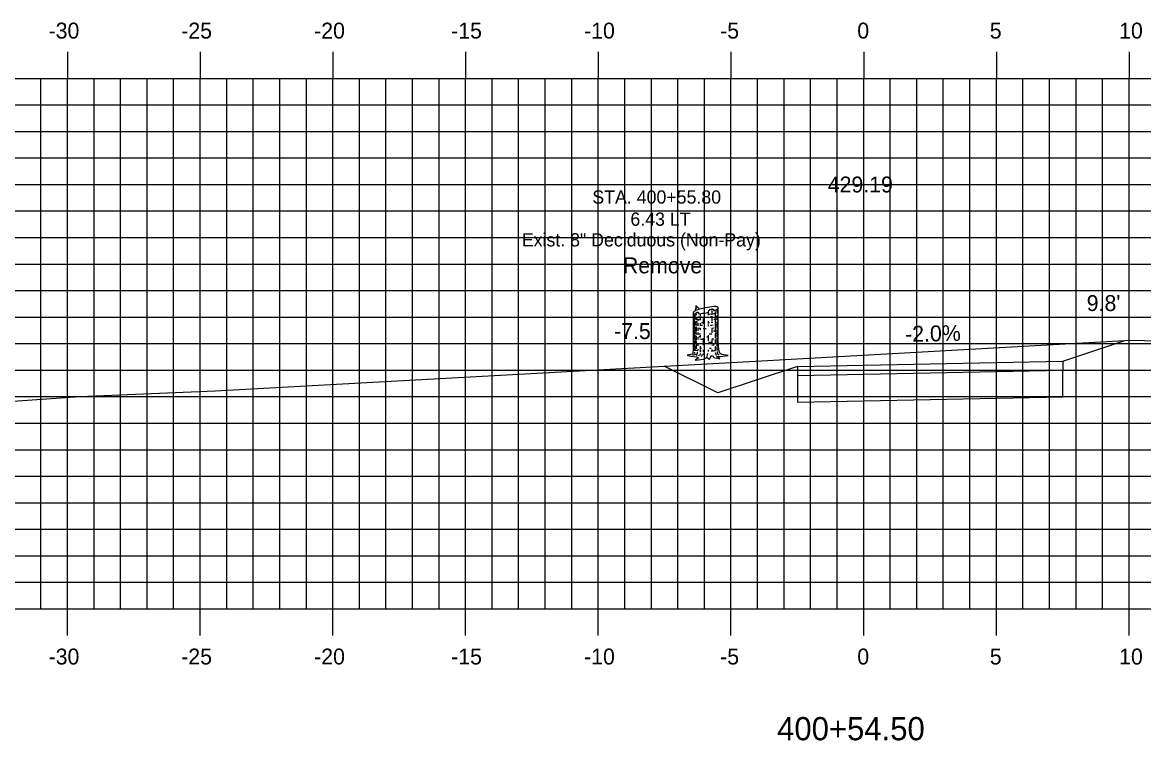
# Model space of a CAD drawing. Extents: x -161 to 764, y 111 to 210.
# Drawn here: x 122.87 to 165.11, y 162.17 to 189.25 of the extents above; entities that cross this region are included whole.
import ezdxf

# ---------------------------------------------------------------- set-up
doc = ezdxf.new("R2010")
doc.units = 0
for name, color, linetype in [('D_Property_Walkway_Paved', 7, 'Continuous'), ('D_Roadway_Centerline_Text', 7, 'Continuous'), ('D_Roadway_SubGrade', 7, 'Continuous'), ('D_Slope_Cut', 7, 'Continuous'), ('D_Text_Monospaced', 7, 'Continuous'), ('D_Text_Standard', 7, 'Continuous'), ('H_V ANNOTATION', 7, 'Continuous'), ('MAJOR', 7, 'Continuous'), ('MINOR', 7, 'Continuous'), ('S_Roadway_Centerline', 7, 'Continuous'), ('S_Trees_Decid_NonPay', 7, 'Continuous')]:
    doc.layers.add(name, color=color, linetype=linetype)

msp = doc.modelspace()

# ---------------------------------------------------------------- linework, layer by layer
at = {"layer": 'D_Property_Walkway_Paved'}
for p, q in [((152.064, 176.281), (162.062, 176.481)), ((152.064, 176.281), (152.064, 175.937)), ((162.062, 176.481), (162.062, 176.137)), ((152.064, 175.937), (162.062, 176.137))]:
    msp.add_line(p, q, dxfattribs=at)
at = {"layer": 'D_Roadway_SubGrade'}
for p, q in [((152.064, 175.937), (152.064, 174.937)), ((162.063, 175.137), (162.062, 176.137)), ((152.064, 174.937), (162.063, 175.137))]:
    msp.add_line(p, q, dxfattribs=at)
at = {"layer": 'D_Slope_Cut'}
for p, q in [((162.062, 176.481), (164.401, 177.26)), ((149.064, 175.281), (147.045, 176.29)), ((152.064, 176.281), (149.064, 175.281))]:
    msp.add_line(p, q, dxfattribs=at)
at = {"layer": 'MAJOR'}
for p, q in [((124.563, 188.143), (124.563, 187.141)), ((129.563, 188.143), (129.563, 187.141)), ((134.563, 188.143), (134.563, 187.141)), ((139.563, 188.143), (139.563, 187.141)), ((144.563, 188.143), (144.563, 187.141)), ((149.563, 188.143), (149.563, 187.141)), ((154.563, 188.143), (154.563, 187.141)), ((159.563, 188.143), (159.563, 187.141)), ((164.563, 188.143), (164.563, 187.141)), ((84.563, 187.141), (224.563, 187.141)), ((84.563, 187.141), (224.563, 187.141)), ((124.563, 167.141), (124.563, 187.141)), ((129.563, 167.141), (129.563, 187.141)), ((134.563, 167.141), (134.563, 187.141)), ((139.563, 167.141), (139.563, 187.141)), ((144.563, 167.141), (144.563, 187.141)), ((149.563, 167.141), (149.563, 187.141)), ((154.563, 167.141), (154.563, 187.141)), ((159.563, 167.141), (159.563, 187.141)), ((164.563, 167.141), (164.563, 187.141)), ((84.563, 182.141), (224.563, 182.141)), ((84.563, 177.141), (224.563, 177.141)), ((84.563, 172.141), (224.563, 172.141)), ((84.563, 167.141), (224.563, 167.141)), ((84.563, 167.141), (224.563, 167.141)), ((124.563, 166.139), (124.563, 167.141)), ((129.563, 166.139), (129.563, 167.141)), ((134.563, 166.139), (134.563, 167.141)), ((139.563, 166.139), (139.563, 167.141)), ((144.563, 166.139), (144.563, 167.141)), ((149.563, 166.139), (149.563, 167.141)), ((154.563, 166.139), (154.563, 167.141)), ((159.563, 166.139), (159.563, 167.141)), ((164.563, 166.139), (164.563, 167.141))]:
    msp.add_line(p, q, dxfattribs=at)
at = {"layer": 'MINOR'}
for p, q in [((123.563, 167.141), (123.563, 187.141)), ((125.563, 167.141), (125.563, 187.141)), ((126.563, 167.141), (126.563, 187.141)), ((127.563, 167.141), (127.563, 187.141)), ((128.563, 167.141), (128.563, 187.141)), ((130.563, 167.141), (130.563, 187.141)), ((131.563, 167.141), (131.563, 187.141)), ((132.563, 167.141), (132.563, 187.141)), ((133.563, 167.141), (133.563, 187.141)), ((135.563, 167.141), (135.563, 187.141)), ((136.563, 167.141), (136.563, 187.141)), ((137.563, 167.141), (137.563, 187.141)), ((138.563, 167.141), (138.563, 187.141)), ((140.563, 167.141), (140.563, 187.141)), ((141.563, 167.141), (141.563, 187.141)), ((142.563, 167.141), (142.563, 187.141)), ((143.563, 167.141), (143.563, 187.141)), ((145.563, 167.141), (145.563, 187.141)), ((146.563, 167.141), (146.563, 187.141)), ((147.563, 167.141), (147.563, 187.141)), ((148.563, 167.141), (148.563, 187.141)), ((150.563, 167.141), (150.563, 187.141)), ((151.563, 167.141), (151.563, 187.141)), ((152.563, 167.141), (152.563, 187.141)), ((153.563, 167.141), (153.563, 187.141)), ((155.563, 167.141), (155.563, 187.141)), ((156.563, 167.141), (156.563, 187.141)), ((157.563, 167.141), (157.563, 187.141)), ((158.563, 167.141), (158.563, 187.141)), ((160.563, 167.141), (160.563, 187.141)), ((161.563, 167.141), (161.563, 187.141)), ((162.563, 167.141), (162.563, 187.141)), ((163.563, 167.141), (163.563, 187.141)), ((84.563, 186.141), (224.563, 186.141)), ((84.563, 185.141), (224.563, 185.141)), ((84.563, 184.141), (224.563, 184.141)), ((84.563, 183.141), (224.563, 183.141)), ((84.563, 181.141), (224.563, 181.141)), ((84.563, 180.141), (224.563, 180.141)), ((84.563, 179.141), (224.563, 179.141)), ((84.563, 178.141), (224.563, 178.141)), ((84.563, 176.141), (224.563, 176.141)), ((84.563, 175.141), (224.563, 175.141)), ((84.563, 174.141), (224.563, 174.141)), ((84.563, 173.141), (224.563, 173.141)), ((84.563, 171.141), (224.563, 171.141)), ((84.563, 170.141), (224.563, 170.141)), ((84.563, 169.141), (224.563, 169.141)), ((84.563, 168.141), (224.563, 168.141))]:
    msp.add_line(p, q, dxfattribs=at)
at = {"layer": 'S_Roadway_Centerline'}
msp.add_lwpolyline([(84.563, 173.937), (86.565, 173.962), (104.807, 174.158), (105.264, 174.178), (106.296, 174.117), (107.265, 173.972), (107.828, 174.003), (110.477, 174.125), (125.033, 175.141), (130.13, 175.365), (150.707, 176.49), (164.616, 177.272), (172.022, 177.096), (179.352, 177.108), (186.535, 177.007), (193.367, 177.096), (200.259, 176.65), (200.943, 176.413), (208.506, 176.123), (214.429, 175.907), (217.362, 175.08), (224.563, 174.564)], dxfattribs=at)
at = {"layer": 'S_Trees_Decid_NonPay'}
for p, q in [((148.402, 178.269), (148.402, 178.191)), ((148.699, 178.322), (148.699, 178.215)), ((148.846, 178.368), (148.846, 178.219)), ((148.965, 178.351), (148.965, 178.05)), ((149.033, 178.437), (149.033, 178.343)), ((148.175, 178.194), (148.175, 178.112)), ((148.175, 178.042), (148.175, 177.912)), ((148.175, 177.89), (148.175, 177.708)), ((148.202, 178.264), (148.202, 178.046)), ((148.202, 177.977), (148.202, 177.826)), ((148.245, 178.259), (148.245, 178.207)), ((148.245, 178.104), (148.245, 178.021)), ((148.245, 177.987), (148.245, 177.912)), ((148.245, 177.885), (148.245, 177.826)), ((148.315, 178.086), (148.315, 177.999)), ((148.315, 177.929), (148.315, 177.807)), ((148.402, 178.104), (148.402, 178.019)), ((148.402, 177.908), (148.402, 177.807)), ((148.52, 178.086), (148.52, 177.885)), ((148.699, 177.987), (148.699, 177.9)), ((148.699, 177.865), (148.699, 177.795)), ((148.846, 178.172), (148.846, 178.003)), ((148.965, 178.021), (148.965, 177.89)), ((148.965, 177.856), (148.965, 177.575)), ((149.033, 178.116), (149.033, 178.034)), ((149.033, 177.964), (149.033, 177.713)), ((148.175, 177.661), (148.175, 177.414)), ((148.202, 177.721), (148.202, 177.643)), ((148.202, 177.616), (148.202, 177.509)), ((148.202, 177.474), (148.202, 177.373)), ((148.245, 177.773), (148.245, 177.592)), ((148.245, 177.56), (148.245, 177.478)), ((148.245, 177.424), (148.245, 177.254)), ((148.315, 177.732), (148.315, 177.618)), ((148.315, 177.556), (148.315, 177.474)), ((148.402, 177.723), (148.402, 177.647)), ((148.402, 177.462), (148.402, 177.364)), ((148.699, 177.462), (148.699, 177.239)), ((148.846, 177.697), (148.846, 177.548)), ((148.965, 177.505), (148.965, 177.361)), ((149.033, 177.63), (149.033, 177.4)), ((148.173, 177.248), (148.174, 176.988)), ((148.175, 177.395), (148.175, 177.301)), ((148.202, 177.347), (148.202, 177.165)), ((148.202, 177.062), (148.202, 176.87)), ((148.245, 177.22), (148.245, 176.941)), ((148.315, 177.387), (148.315, 177.29)), ((148.315, 177.161), (148.315, 177.062)), ((148.402, 177.04), (148.402, 176.815)), ((148.52, 177.348), (148.52, 177.161)), ((148.52, 177.13), (148.52, 177.077)), ((148.846, 177.279), (148.846, 177.126)), ((148.965, 177.29), (148.965, 177.149)), ((148.965, 177.048), (148.965, 176.866)), ((149.033, 177.33), (149.033, 177.169)), ((149.033, 177.153), (149.033, 177.048)), ((149.033, 177.011), (149.033, 176.887)), ((148.122, 176.702), (148.189, 176.733)), ((148.204, 176.823), (148.169, 176.772)), ((148.175, 176.949), (148.175, 176.875)), ((148.245, 176.888), (148.245, 176.863)), ((148.315, 176.933), (148.315, 176.874)), ((148.52, 176.901), (148.52, 176.811)), ((148.659, 176.62), (148.694, 176.765)), ((148.699, 176.906), (148.699, 176.84)), ((148.846, 176.914), (148.846, 176.836)), ((148.966, 176.807), (149.007, 176.71))]:
    msp.add_line(p, q, dxfattribs=at)
for points in [[(148.134, 178.301), (148.134, 176.889), (148.111, 176.741), (147.908, 176.698), (148.048, 176.662), (148.266, 176.644), (148.336, 176.601), (148.214, 176.512), (148.546, 176.555), (148.659, 176.62), (148.752, 176.559), (148.808, 176.638), (148.799, 176.675), (148.861, 176.677), (148.913, 176.62), (149.145, 176.568), (149.018, 176.656), (149.149, 176.658), (149.458, 176.696), (149.219, 176.727), (149.141, 176.784), (149.102, 176.906), (149.085, 177.26), (149.085, 178.493)], [(148.229, 178.382), (148.233, 178.477), (148.247, 178.45), (148.247, 178.571), (148.268, 178.508), (148.283, 178.54), (148.299, 178.485), (148.315, 178.502), (148.334, 178.493), (148.353, 178.426)], [(148.251, 178.258), (148.268, 178.32), (148.291, 178.308), (148.321, 178.343), (148.355, 178.265)], [(148.721, 178.327), (148.729, 178.394), (148.754, 178.399), (148.762, 178.433), (148.793, 178.419), (148.808, 178.433), (148.832, 178.41), (148.855, 178.419), (148.867, 178.468), (148.875, 178.425), (148.906, 178.433), (148.909, 178.382)], [(148.173, 176.749), (148.252, 176.733), (148.268, 176.689)], [(148.252, 176.733), (148.295, 176.767), (148.303, 176.815)], [(148.399, 176.767), (148.394, 176.698), (148.33, 176.685)], [(148.511, 176.761), (148.511, 176.725), (148.46, 176.694), (148.443, 176.644)], [(149.036, 176.844), (149.044, 176.767), (149.123, 176.718)]]:
    msp.add_lwpolyline(points, dxfattribs=at)
for centre, radius, start, end in [((148.158, 178.301), 0.0237, 161.8277, 175.7722), ((148.152, 178.302), 0.0179, 175.7722, 191.8277), ((148.152, 178.302), 0.0179, 191.8277, 207.8832), ((148.167, 178.298), 0.0336, 143.0514, 161.8277), ((148.157, 178.304), 0.0237, 207.8832, 221.8277), ((148.164, 178.311), 0.0336, 221.8277, 240.604), ((148.215, 178.262), 0.0935, 131.8277, 143.0514), ((148.194, 178.363), 0.0935, 240.604, 251.8277), ((148.367, 178.092), 0.322, 109.7098, 131.8277), ((148.265, 178.58), 0.322, 251.8277, 267.5521), ((149.104, 176.035), 2.507, 101.8277, 109.7098), ((148.115, 180.76), 2.507, 275.4987, 281.8277), ((149.104, 176.035), 2.507, 93.9457, 101.8277), ((148.115, 180.76), 2.507, 281.8277, 284.0013), ((148.61, 180.607), 2.356, 276.7201, 278.1032), ((148.115, 180.76), 2.507, 288.4719, 289.7098), ((148.954, 178.215), 0.322, 71.8277, 93.9457), ((148.896, 178.597), 0.326, 278.1032, 282.1964), ((148.852, 178.703), 0.322, 289.7098, 311.8277), ((148.896, 178.597), 0.326, 291.6757, 300), ((149.025, 178.432), 0.0935, 60.604, 71.8277), ((149.01, 178.4), 0.0984, 300, 311.2506), ((149.004, 178.533), 0.0935, 311.8277, 323.0514), ((149.054, 178.484), 0.0336, 41.8277, 60.604), ((149.052, 178.353), 0.0356, 311.2506, 330), ((149.062, 178.49), 0.0237, 27.8832, 41.8277), ((149.052, 178.497), 0.0336, 323.0514, 341.8277), ((149.061, 178.347), 0.0252, 330, 343.9485), ((149.067, 178.493), 0.0179, 11.8277, 27.8832), ((149.067, 178.493), 0.0179, 355.7722, 11.8277), ((149.061, 178.494), 0.0237, 341.8277, 355.7722), ((149.067, 178.346), 0.0191, 360, 16.0515), ((149.067, 178.346), 0.0191, 343.9485, 360), ((148.154, 178.233), 0.0191, 173.8872, 180), ((148.154, 178.233), 0.0191, 180, 196.0515), ((148.16, 178.234), 0.0252, 196.0515, 210), ((148.154, 178.132), 0.0191, 173.8872, 180), ((148.154, 178.132), 0.0191, 180, 196.0515), ((148.16, 178.133), 0.0252, 196.0515, 210), ((148.154, 178.029), 0.0191, 173.8872, 180), ((148.154, 178.029), 0.0191, 180, 196.0515), ((148.154, 177.924), 0.0191, 173.8872, 180), ((148.154, 177.924), 0.0191, 180, 196.0515), ((148.16, 177.925), 0.0252, 196.0515, 210), ((148.169, 178.239), 0.0356, 210, 228.7494), ((148.169, 178.139), 0.0356, 210, 228.7494), ((148.169, 177.931), 0.0356, 210, 228.7494), ((148.21, 178.287), 0.0984, 228.7494, 240), ((148.21, 178.186), 0.0984, 228.7494, 240), ((148.21, 177.978), 0.0984, 228.7494, 240), ((148.324, 178.484), 0.326, 240, 248.0494), ((148.324, 178.383), 0.326, 240, 248.0494), ((148.324, 178.175), 0.326, 240, 248.0494), ((148.324, 178.28), 0.326, 255.9618, 261.8968), ((148.324, 178.175), 0.326, 255.9618, 261.8968), ((148.324, 178.383), 0.326, 260.9146, 261.8968), ((148.61, 180.393), 2.356, 261.8968, 264.9353), ((148.61, 180.29), 2.356, 261.8968, 262.6162), ((148.61, 180.185), 2.356, 261.8968, 262.8131), ((148.61, 180.494), 2.356, 263.2266, 266.8519), ((148.61, 180.29), 2.356, 266.0259, 267.8019), ((148.61, 180.393), 2.356, 267.8019, 269.1881), ((148.61, 180.607), 2.356, 272.1614, 274.76), ((148.61, 180.29), 2.356, 272.1614, 273.4964), ((148.61, 180.494), 2.356, 272.6327, 275.758), ((148.61, 180.185), 2.356, 274.3638, 276.7318), ((148.61, 180.29), 2.356, 275.0054, 276.6587), ((148.61, 180.393), 2.356, 277.4481, 278.1032), ((148.896, 178.383), 0.326, 278.1032, 289.5833), ((148.896, 178.484), 0.326, 282.1964, 299.0901), ((148.896, 178.28), 0.326, 282.1964, 288.3169), ((148.896, 178.175), 0.326, 282.1964, 294.8455), ((148.896, 178.383), 0.326, 296.4281, 300), ((148.896, 178.28), 0.326, 296.757, 300), ((149.01, 178.186), 0.0984, 300, 311.2506), ((149.01, 178.083), 0.0984, 300, 311.2506), ((149.052, 178.139), 0.0356, 311.2506, 330), ((149.052, 178.036), 0.0356, 311.2506, 330), ((149.061, 178.133), 0.0252, 330, 343.9485), ((149.061, 178.03), 0.0252, 330, 343.9485), ((149.067, 178.132), 0.0191, 360, 16.0515), ((149.067, 178.132), 0.0191, 343.9485, 360), ((149.067, 178.029), 0.0191, 360, 16.0515), ((149.067, 178.029), 0.0191, 343.9485, 360), ((148.153, 177.694), 0.0191, 173.8872, 180), ((148.153, 177.694), 0.0191, 180, 196.0515), ((148.154, 177.809), 0.0191, 173.8872, 180), ((148.154, 177.809), 0.0191, 180, 196.0515), ((148.16, 177.81), 0.0252, 196.0515, 210), ((148.159, 177.696), 0.0252, 196.0515, 210), ((148.154, 177.489), 0.0191, 173.8872, 180), ((148.154, 177.489), 0.0191, 180, 196.0515), ((148.16, 177.491), 0.0252, 196.0515, 210), ((148.168, 177.701), 0.0356, 210, 228.7494), ((148.156, 177.594), 0.0191, 173.8872, 180), ((148.156, 177.594), 0.0191, 180, 196.0515), ((148.169, 177.816), 0.0356, 210, 228.7494), ((148.162, 177.596), 0.0252, 196.0515, 210), ((148.169, 177.496), 0.0356, 210, 228.7494), ((148.171, 177.601), 0.0356, 210, 228.7494), ((148.21, 177.863), 0.0984, 228.7494, 240), ((148.209, 177.748), 0.0984, 228.7494, 240), ((148.21, 177.543), 0.0984, 228.7494, 240), ((148.213, 177.648), 0.0984, 228.7494, 240), ((148.323, 177.946), 0.326, 240, 242.9942), ((148.324, 178.06), 0.326, 240, 255.9618), ((148.324, 177.741), 0.326, 240, 242.8475), ((148.326, 177.845), 0.326, 240, 247.5951), ((148.323, 177.946), 0.326, 248.1902, 256.0964), ((148.324, 177.741), 0.326, 248.0494, 255.9618), ((148.61, 180.07), 2.356, 262.8131, 264.9353), ((148.613, 179.855), 2.356, 262.7545, 265.0266), ((148.61, 180.185), 2.356, 264.9353, 266.9933), ((148.61, 180.07), 2.356, 267.586, 270), ((148.61, 180.07), 2.356, 270, 270.4422), ((148.613, 179.855), 2.356, 273.1471, 275.6557), ((148.61, 180.07), 2.356, 275.2089, 277.3412), ((148.609, 179.956), 2.356, 277.1385, 278.1032), ((148.896, 177.946), 0.326, 278.1032, 282.3301), ((148.899, 177.845), 0.326, 283.0921, 300), ((148.896, 177.946), 0.326, 292.1344, 300), ((148.896, 178.06), 0.326, 294.8455, 300), ((148.896, 177.741), 0.326, 294.8455, 300), ((149.01, 177.863), 0.0984, 300, 311.2506), ((149.009, 177.748), 0.0984, 300, 311.2506), ((149.01, 177.543), 0.0984, 300, 311.2506), ((149.051, 177.701), 0.0356, 311.2506, 330), ((149.052, 177.816), 0.0356, 311.2506, 330), ((149.052, 177.496), 0.0356, 311.2506, 330), ((149.061, 177.81), 0.0252, 330, 343.9485), ((149.06, 177.696), 0.0252, 330, 343.9485), ((149.061, 177.491), 0.0252, 330, 343.9485), ((149.066, 177.694), 0.0191, 360, 16.0515), ((149.066, 177.694), 0.0191, 343.9485, 360), ((149.067, 177.809), 0.0191, 360, 16.0515), ((149.067, 177.809), 0.0191, 343.9485, 360), ((149.067, 177.489), 0.0191, 360, 16.0515), ((149.067, 177.489), 0.0191, 343.9485, 360), ((149.069, 177.594), 0.0191, 360, 16.0515), ((148.154, 177.399), 0.0191, 173.8872, 180), ((148.158, 177.17), 0.0191, 173.8872, 180), ((148.158, 177.17), 0.0191, 180, 196.0515), ((148.164, 177.172), 0.0252, 196.0515, 210), ((148.173, 177.177), 0.0356, 210, 228.7494), ((148.214, 177.224), 0.0984, 228.7494, 240), ((148.333, 177.311), 0.326, 240, 246.3456), ((148.324, 177.537), 0.326, 248.0494, 255.9618), ((148.328, 177.421), 0.326, 255.2259, 261.8968), ((148.614, 179.431), 2.356, 261.8968, 262.7137), ((148.61, 179.751), 2.356, 263.572, 264.9353), ((148.61, 179.66), 2.356, 264.7274, 267.8019), ((148.61, 179.751), 2.356, 270.9946, 272.1614), ((148.61, 179.547), 2.356, 272.531, 275.758), ((148.61, 179.66), 2.356, 275.5135, 277.4157), ((148.614, 179.431), 2.356, 275.5148, 277.7774), ((148.896, 177.65), 0.326, 286.0817, 298.061), ((148.9, 177.421), 0.326, 294.0625, 300), ((148.905, 177.311), 0.326, 298.0903, 300), ((149.014, 177.224), 0.0984, 300, 311.2506), ((149.019, 177.114), 0.0984, 300, 311.2506), ((149.056, 177.177), 0.0356, 311.2506, 330), ((149.061, 177.066), 0.0356, 311.2506, 330), ((149.065, 177.172), 0.0252, 330, 343.9485), ((149.071, 177.17), 0.0191, 360, 16.0515), ((149.071, 177.17), 0.0191, 343.9485, 360), ((149.07, 177.061), 0.0252, 330, 343.9485), ((149.075, 177.06), 0.0191, 360, 16.0515), ((149.075, 177.06), 0.0191, 343.9485, 360), ((148.168, 176.949), 0.0191, 173.8872, 180), ((148.168, 176.949), 0.0191, 180, 196.0515), ((148.174, 176.951), 0.0252, 196.0515, 210), ((148.183, 176.956), 0.0356, 210, 228.7494), ((148.225, 177.003), 0.0984, 228.7494, 240), ((148.338, 177.201), 0.326, 245.2906, 261.8968), ((148.625, 179.211), 2.356, 261.8968, 262.4597), ((148.619, 179.321), 2.356, 264.7171, 265.8136), ((148.625, 179.211), 2.356, 264.5833, 265.4449), ((148.619, 179.321), 2.356, 273.1842, 275.0911), ((148.625, 179.211), 2.356, 276.4667, 278.1032), ((148.911, 177.201), 0.326, 278.1032, 279.6166), ((148.911, 177.201), 0.326, 292.0839, 300), ((149.025, 177.003), 0.0984, 300, 311.2506), ((149.066, 176.956), 0.0356, 311.2506, 330), ((149.075, 176.951), 0.0252, 330, 343.9485), ((149.081, 176.949), 0.0191, 360, 16.0515), ((149.081, 176.949), 0.0191, 343.9485, 360)]:
    msp.add_arc(centre, radius, start, end, dxfattribs=at)

# ---------------------------------------------------------------- texts
at = {"layer": 'D_Roadway_Centerline_Text'}
msp.add_text('429.19', height=0.6, dxfattribs=at).set_placement((153.209, 182.839))
at = {"layer": 'D_Text_Monospaced'}
for s, height, p in [('STA. 400+55.80', 0.49998, (144.339, 182.417)), ('6.43 LT', 0.5, (145.773, 181.583)), ('Exist. 8" Deciduous (Non-Pay)', 0.49998, (141.681, 180.803))]:
    msp.add_text(s, height=height, dxfattribs=at).set_placement(p)
at = {"layer": 'D_Text_Standard'}
for s, p in [('Remove', (145.49, 179.789)), ("9.8'", (162.966, 178.368)), ('-7.5', (145.157, 177.312))]:
    msp.add_text(s, height=0.6, dxfattribs=at).set_placement(p)
msp.add_text('-2.0%', height=0.6, rotation=1.1458, dxfattribs=at).set_placement((156.13, 177.202))
at = {"layer": 'H_V ANNOTATION'}
for s, height, p in [('-30', 0.6, (123.851, 188.641)), ('-25', 0.6, (128.849, 188.641)), ('-20', 0.6, (133.857, 188.641)), ('-10', 0.6, (144.028, 188.641)), ('0', 0.6, (154.322, 188.641)), ('10', 0.6, (164.188, 188.641)), ('-15', 0.6, (139.02, 188.641)), ('-5', 0.6, (149.154, 188.641)), ('5', 0.6, (159.314, 188.641)), ('-30', 0.6, (123.851, 165.041)), ('-25', 0.6, (128.849, 165.041)), ('-20', 0.6, (133.857, 165.041)), ('-15', 0.6, (139.02, 165.041)), ('-10', 0.6, (144.028, 165.041)), ('-5', 0.6, (149.154, 165.041)), ('0', 0.6, (154.322, 165.041)), ('5', 0.6, (159.314, 165.041)), ('10', 0.6, (164.188, 165.041)), ('400+54.50', 0.875, (151.301, 162.184))]:
    msp.add_text(s, height=height, rotation=360, dxfattribs=at).set_placement(p)

doc.saveas('drawing.dxf')
